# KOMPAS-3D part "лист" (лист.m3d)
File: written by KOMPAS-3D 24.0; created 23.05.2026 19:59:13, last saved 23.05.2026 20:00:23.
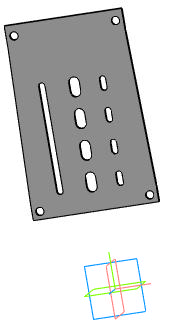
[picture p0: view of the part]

Document properties: Автор: R2D2; Полное имя файла: E:\Работа\Зайцев\GVKR1331M-1W-Fb-2P Задвижка шиберная с выдвижным штоком DN.ru Ду50-300 Ру16-10-6 с пневмоприводом\исходные материалы\DN65\лист.m3d

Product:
- Part/product: лист
    Масса: 0.611304
    Раздел спецификации: Прочие изделия
    Примечание: D040-08800

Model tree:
1. Эскиз:1  (with: Грань.Элемент выдавливания:15, Вершина.Элемент выдавливания:15, Ребро.Элемент выдавливания:15, Вершина.Элемент выдавливания:5, Ребро.Элемент выдавливания:5, Вершина.Скругление:1)
2. Элемент выдавливания:1
3. Эскиз:2  (with: Грань.Элемент выдавливания:1)
4. Элемент выдавливания:2
5. Эскиз:3  (with: Грань.Элемент выдавливания:1, Ребро.Элемент выдавливания:1)
6. Элемент выдавливания:3
7. Эскиз:4  (with: Грань.Элемент выдавливания:1, Вершина.Элемент выдавливания:2)
8. Элемент выдавливания:4
9. Массив по сетке:1  (with: Элемент выдавливания:4, Эскиз:4, Ребро.Элемент выдавливания:2)  (4 pattern instances)
     Шаг 1 = 30; Угол раствора = 90
10. Зеркальный массив:1
11. Экземпляр ( 1 )
12. Экземпляр ( 2 )  (with: Элемент выдавливания:3)

Expressions: v444*0.6
Referenced files in E:\Работа\Зайцев\GVKR1331M-1W-Fb-2P Задвижка шиберная с выдвижным штоком DN.ru Ду50-300 Ру16-10-6 с пневмоприводом\исходные материалы\DN65\: GVKR1331M-1W-Fb-2P Задвижка шиберная с выдвижным штоком DN.ru Ду65 Ру16.a3d
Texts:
  Затвор дисковый DN.ru Ду Ру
